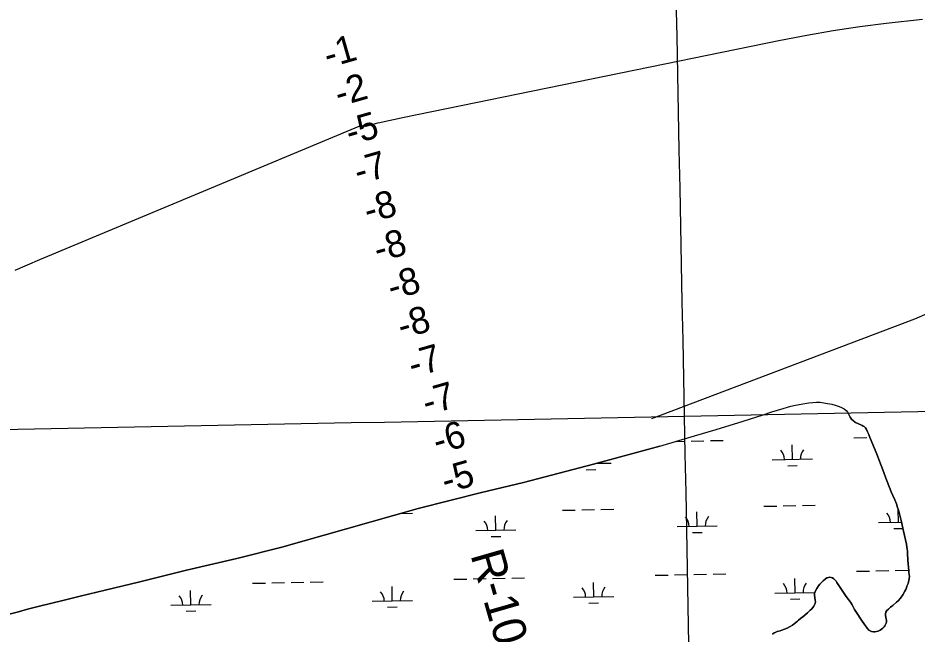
# Model space of a CAD drawing. Extents: x 3989314 to 4027622, y 243956 to 270014.
# Drawn here: x 3997154 to 3999395, y 255017 to 256552 of the extents above; entities that cross this region are included whole.
import ezdxf

# ---------------------------------------------------------------- set-up
doc = ezdxf.new("R2010")
doc.units = 0
for name, color, linetype in [('V-GRID-MAJR', 7, 'Continuous'), ('V-RIVR-EDGE', 7, 'Continuous'), ('V-RIVR-RANG', 7, 'Continuous'), ('V-RIVR-RANG-IDEN', 7, 'Continuous'), ('V-TOPO-MINR', 7, 'Continuous'), ('V-TOPO-SHOR', 7, 'Continuous'), ('V-WETL-SWMP', 7, 'Continuous')]:
    doc.layers.add(name, color=color, linetype=linetype)

msp = doc.modelspace()

# ---------------------------------------------------------------- linework, layer by layer
at = {"layer": 'V-GRID-MAJR'}
for points in [[(3998934.301, 249501.96300000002), (3998815.338, 255559.756), (3998696.338, 261619.472), (3998577.3370000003, 267679.178), (3998577.299, 267681.11100000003)], [(3993497.629, 255455.714), (3998815.338, 255559.756), (4004133.032, 255664.571), (4009450.711, 255770.161), (4014768.3740000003, 255876.52300000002), (4020086.022, 255983.659), (4025403.6550000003, 256091.568)]]:
    msp.add_spline(points, degree=3, dxfattribs=at)
at = {"layer": 'V-RIVR-EDGE'}
for points in [[(3998754.062, 255484.529), (3998840.193, 255510.33000000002), (3998894.25, 255526.067), (3998961.758, 255546.83800000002), (3999011.549, 255562.57700000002), (3999033.018, 255570.06), (3999060.824, 255578.96300000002), (3999072.073, 255582.18600000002), (3999080.091, 255584.38), (3999092.248, 255587.087), (3999115.268, 255591.339), (3999124.965, 255592.75400000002), (3999134.791, 255593.651), (3999144.233, 255594.29200000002), (3999153.67, 255594.286)], [(3998754.062, 255484.529), (3998588.223, 255440.24300000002), (3998414.323, 255394.41700000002), (3998309.677, 255369.211)], [(3998309.677, 255369.211), (3998151.833, 255329.68), (3997973.356, 255278.578), (3997811.755, 255233.279), (3997699.774, 255204.988), (3997574.289, 255175.671), (3997458.34, 255146.575), (3997371.574, 255125.69700000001), (3997309.028, 255111.04), (3997269.123, 255101.009), (3997207.771, 255085.956), (3997177.989, 255078.331), (3997155.356, 255072.117), (3997092.221, 255056.266)], [(3999034.941, 255016.748), (3999038.677, 255019.41400000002), (3999041.378, 255020.93600000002), (3999046.387, 255022.695), (3999053.451, 255024.82700000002), (3999057.8170000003, 255026.336), (3999070.924, 255031.635), (3999078.383, 255035.43), (3999084.685, 255038.848), (3999092.934, 255045.844), (3999096.799, 255048.764), (3999099.764, 255051.437), (3999104.272, 255055.123), (3999110.197, 255059.313), (3999115.223, 255063.51200000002), (3999121.926, 255069.363), (3999128.7600000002, 255075.853), (3999132.631, 255079.673), (3999135.342, 255082.859), (3999137.931, 255086.55800000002), (3999139.489, 255089.753), (3999140.5360000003, 255092.95), (3999141.593, 255097.556), (3999141.2320000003, 255101.404), (3999139.262, 255113.592), (3999139.541, 255116.922), (3999140.075, 255120.37900000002), (3999141.64, 255124.34100000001), (3999144.753, 255130.08800000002), (3999149.154, 255136.72400000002), (3999152.386, 255140.932), (3999154.968, 255143.863), (3999160.645, 255149.59100000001), (3999166.9590000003, 255154.676), (3999170.1750000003, 255156.45), (3999173.773, 255157.707), (3999177.619, 255158.068), (3999180.949, 255157.78900000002), (3999184.017, 255156.745), (3999187.335, 255154.41400000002), (3999190.2660000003, 255151.70500000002), (3999193.061, 255148.354), (3999195.095, 255145.522), (3999218.571, 255110.122), (3999223.9080000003, 255103.165), (3999228.602, 255096.085), (3999232.915, 255089.136), (3999239.1210000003, 255077.946), (3999243.815, 255070.481), (3999256.633, 255051.431), (3999263.484, 255040.619), (3999266.279, 255037.14), (3999268.563, 255033.537), (3999270.34, 255031.09), (3999274.7970000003, 255026.44700000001), (3999277.7290000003, 255024.377), (3999280.924, 255023.074), (3999286.171, 255021.886), (3999289.632, 255021.991), (3999293.997, 255022.859), (3999298.234, 255024.114), (3999303.116, 255026.132), (3999309.433, 255031.34600000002), (3999312.656, 255034.655), (3999314.596, 255037.078), (3999316.412, 255040.39800000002), (3999317.715, 255043.46600000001), (3999318.505, 255047.05000000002), (3999318.528, 255050.124), (3999317.915, 255054.61500000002), (3999316.048, 255062.957), (3999315.818, 255066.932), (3999317.129, 255071.409), (3999319.847, 255075.364)], [(3999319.847, 255075.364), (3999323.33, 255078.929), (3999328.745, 255083.764), (3999331.707, 255086.05000000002), (3999334.541, 255087.95500000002), (3999343.823, 255096.22400000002), (3999347.433, 255099.661), (3999353.628, 255106.413), (3999359.322, 255114.579), (3999364.505, 255123.38700000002), (3999366.5840000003, 255127.602), (3999368.2800000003, 255131.95), (3999369.588, 255136.04200000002), (3999372.873, 255142.685)]]:
    msp.add_lwpolyline(points, dxfattribs=at)
at = {"layer": 'V-TOPO-MINR'}
for points in [[(3999408.762457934, 256548.33119505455), (3999318.2285450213, 256538.05911623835), (3999251.9537520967, 256529.63691733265), (3999185.8666386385, 256520.03456851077), (3999120.061044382, 256508.66199481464), (3999054.4431295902, 256496.1092712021), (3998112.928943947, 256302.860964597), (3998101.50308511, 256300.49334681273), (3998090.083296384, 256298.09706968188), (3998078.672612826, 256295.65780353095), (3998067.2679993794, 256293.18987803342), (3998056.40921246, 256290.818654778), (3998050.451044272, 256289.46448715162), (3998044.5095303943, 256288.04321957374), (3998038.592997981, 256286.52130206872), (3998032.693119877, 256284.9322846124), (3998020.949933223, 256281.662323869), (3998020.93407441, 256281.65891151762), (3998020.9020265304, 256281.65652885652), (3998020.804536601, 256281.66769528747), (3998020.772078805, 256281.6722006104), (3998020.755873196, 256281.6746210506), (3998014.8955401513, 256282.57647257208), (3998011.979755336, 256282.77903929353), (3998009.1022672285, 256282.66742615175), (3998006.2822241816, 256282.08454321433), (3998003.5004778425, 256281.18748041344), (3997208.3145577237, 255949.39935462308), (3997146.5055219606, 255922.6533061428)], [(3998734.21, 255554.1), (3999389.2295445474, 255802.18688364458), (3999419.692060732, 255815.1619594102)]]:
    msp.add_lwpolyline(points, dxfattribs=at)
at = {"layer": 'V-TOPO-SHOR'}
for points in [[(3999153.67, 255594.286), (3999166.988, 255592.465), (3999182.241, 255589.86800000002), (3999191.034, 255587.407), (3999198.529, 255584.945), (3999205.253, 255582.352), (3999213.007, 255578.34), (3999218.0470000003, 255573.812), (3999221.4050000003, 255569.413), (3999228.379, 255557.125)], [(3999361.267, 255272.881), (3999354.949, 255300.046), (3999351.47, 255316.602), (3999348.629, 255325.658), (3999346.1780000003, 255332.256), (3999343.466, 255340.795), (3999339.464, 255351.014), (3999334.815, 255362.01200000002), (3999330.4250000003, 255371.068), (3999320.3540000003, 255396.553), (3999317.256, 255405.22100000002), (3999311.835, 255418.934), (3999294.9220000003, 255464.602), (3999280.591, 255499.404), (3999277.492, 255506.39), (3999274.522, 255513.894), (3999271.5530000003, 255520.492), (3999268.5810000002, 255526.44400000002), (3999265.9960000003, 255530.714), (3999264.446, 255532.39500000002), (3999262.896, 255533.69), (3999260.438, 255534.986), (3999257.8540000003, 255536.151), (3999254.4930000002, 255537.964), (3999241.562, 255543.923), (3999239.106, 255545.347), (3999237.038, 255547.03), (3999231.738, 255552.337), (3999228.379, 255557.125)], [(3999372.873, 255142.685), (3999375.171, 255154.373), (3999375.642, 255160.863), (3999375.4110000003, 255164.624), (3999374.43, 255171.208), (3999374.364, 255174.36800000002), (3999372.23, 255200.52300000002), (3999371.321, 255218.298), (3999370.842, 255223.17), (3999369.537, 255232.83000000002), (3999368.222, 255240.529), (3999361.267, 255272.881)]]:
    msp.add_lwpolyline(points, dxfattribs=at)
at = {"layer": 'V-WETL-SWMP'}
for p, q in [((3999092.248, 255587.087), (3999115.267, 255591.33800000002)), ((3999115.267, 255591.33800000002), (3999124.965, 255592.753)), ((3999124.965, 255592.75300000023), (3999134.792, 255593.65100000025)), ((3999134.792, 255593.651), (3999144.2320000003, 255594.291)), ((3999144.2320000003, 255594.291), (3999153.67, 255594.285)), ((3999153.67, 255594.285), (3999166.987, 255592.465)), ((3999166.987, 255592.465), (3999182.242, 255589.86900000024)), ((3999182.242, 255589.86900000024), (3999191.0330000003, 255587.40600000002)), ((3999011.549, 255562.57600000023), (3999033.018, 255570.06100000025)), ((3999033.018, 255570.06100000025), (3999060.823, 255578.96300000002)), ((3999060.823, 255578.96300000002), (3999072.074, 255582.187)), ((3999072.074, 255582.187), (3999080.092, 255584.38)), ((3999080.092, 255584.38000000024), (3999092.248, 255587.087)), ((3999191.0330000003, 255587.40600000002), (3999198.5300000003, 255584.94400000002)), ((3999198.5300000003, 255584.94400000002), (3999205.252, 255582.35300000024)), ((3999205.252, 255582.35300000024), (3999213.007, 255578.34000000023)), ((3999213.007, 255578.34000000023), (3999218.0470000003, 255573.81100000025)), ((3999218.0470000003, 255573.81100000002), (3999221.4050000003, 255569.412)), ((3999221.4050000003, 255569.412), (3999228.379, 255557.12400000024)), ((3998894.25, 255526.06600000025), (3998961.758, 255546.83700000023)), ((3998961.758, 255546.83700000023), (3999011.549, 255562.57600000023)), ((3999228.379, 255557.12400000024), (3999231.738, 255552.336)), ((3999231.738, 255552.336), (3999237.037, 255547.02999999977)), ((3999237.037, 255547.03000000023), (3999239.106, 255545.34700000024)), ((3999239.106, 255545.347), (3999241.562, 255543.92299999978)), ((3999241.562, 255543.923), (3999254.492, 255537.964)), ((3998840.1920000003, 255510.33000000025), (3998894.25, 255526.06600000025)), ((3999254.492, 255537.964), (3999257.853, 255536.15100000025)), ((3999257.853, 255536.15100000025), (3999260.4390000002, 255534.98500000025)), ((3999260.4390000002, 255534.98500000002), (3999262.895, 255533.69)), ((3999262.895, 255533.69), (3999264.447, 255532.396)), ((3999264.447, 255532.396), (3999265.997, 255530.71300000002)), ((3999265.997, 255530.71300000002), (3999268.5810000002, 255526.443)), ((3999268.5810000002, 255526.443), (3999271.552, 255520.49200000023)), ((3999271.552, 255520.49200000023), (3999274.522, 255513.894)), ((3998754.061, 255484.53), (3998840.1920000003, 255510.33000000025)), ((3998831.8552527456, 255497.66252674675), (3998863.8488999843, 255498.3001288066)), ((3998879.8457236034, 255498.61892983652), (3998911.839370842, 255499.25653189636)), ((3999237.6826703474, 255505.7502697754), (3999269.676317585, 255506.38787183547)), ((3999274.522, 255513.894), (3999277.491, 255506.39)), ((3999277.491, 255506.39), (3999280.591, 255499.40400000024)), ((3999280.591, 255499.40400000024), (3999294.923, 255464.602)), ((3998588.223, 255440.24300000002), (3998754.061, 255484.53)), ((3998795.4828693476, 255496.93766076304), (3998815.858429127, 255497.34372571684)), ((3999084.1323981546, 255451.93808771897), (3999083.415095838, 255487.9309408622)), ((3999294.923, 255464.602), (3999311.8340000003, 255418.93500000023)), ((3998414.323, 255394.418), (3998588.223, 255440.24300000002)), ((3998595.555848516, 255442.20123552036), (3998632.314112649, 255442.9337917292)), ((3999034.1423243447, 255450.94183450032), (3999134.122471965, 255452.93434093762)), ((3999072.4422441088, 255436.27105036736), (3999096.437479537, 255436.74925191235)), ((3998570.633884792, 255426.27050115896), (3998594.6291202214, 255426.74870270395)), ((3999311.8340000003, 255418.93500000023), (3999317.256, 255405.22100000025)), ((3998309.676, 255369.211), (3998414.323, 255394.418)), ((3999317.256, 255405.22100000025), (3999320.3540000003, 255396.554)), ((3999320.3540000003, 255396.554), (3999330.4250000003, 255371.068)), ((3998151.833, 255329.68100000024), (3998309.676, 255369.21100000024)), ((3999330.4250000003, 255371.068), (3999334.816, 255362.011)), ((3999334.816, 255362.011), (3999339.464, 255351.014)), ((3999339.464, 255351.014), (3999343.467, 255340.794)), ((3997973.3570000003, 255278.57800000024), (3998151.833, 255329.68100000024)), ((3998511.230602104, 255325.06579538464), (3998543.224249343, 255325.70339744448)), ((3998559.221072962, 255326.02219847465), (3998591.2147202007, 255326.65980053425)), ((3998607.2115438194, 255326.97860156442), (3998639.205191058, 255327.61620362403)), ((3998846.9332483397, 255285.31680109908), (3998846.215946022, 255321.30965424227)), ((3999013.0389614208, 255335.06634459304), (3999045.032608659, 255335.70394665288)), ((3999061.029432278, 255336.02274768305), (3999093.0230795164, 255336.66034974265)), ((3999109.0199031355, 255336.97915077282), (3999141.013550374, 255337.61675283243)), ((3999343.467, 255340.794), (3999346.177, 255332.256)), ((3999346.177, 255332.256), (3999348.63, 255325.65800000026)), ((3999348.741607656, 255295.31735030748), (3999348.109021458, 255327.05931121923)), ((3999348.63, 255325.65800000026), (3999351.469, 255316.602)), ((3998107.622745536, 255317.02228603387), (3998137.396831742, 255317.61565441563)), ((3998345.124889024, 255275.31625189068), (3998344.4075867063, 255311.30910503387)), ((3999351.469, 255316.602), (3999354.949, 255300.045)), ((3999354.949, 255300.045), (3999361.268, 255272.88)), ((3997811.754, 255233.27800000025), (3997973.3570000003, 255278.57800000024)), ((3998295.1348152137, 255274.31999867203), (3998395.1149628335, 255276.31250510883)), ((3998796.9431745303, 255284.32054788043), (3998896.9233221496, 255286.31305431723)), ((3999298.751533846, 255294.32109708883), (3999356.015006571, 255295.4623020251)), ((3999337.0514536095, 255279.65031295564), (3999359.5886424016, 255280.09945705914)), ((3998333.434734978, 255259.6492145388), (3998357.4299704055, 255260.12741608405)), ((3998835.243094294, 255269.64976374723), (3998859.238329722, 255270.12796529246)), ((3999361.268, 255272.88), (3999368.222, 255240.52800000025)), ((3997699.775, 255204.98700000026), (3997811.754, 255233.27800000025)), ((3999368.222, 255240.52800000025), (3999369.538, 255232.831)), ((3999369.538, 255232.831), (3999370.841, 255223.169)), ((3999370.841, 255223.169), (3999371.322, 255218.297)), ((3999371.322, 255218.297), (3999372.23, 255200.52300000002)), ((3997574.29, 255175.67000000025), (3997699.775, 255204.98700000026)), ((3999372.23, 255200.52300000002), (3999374.364, 255174.36900000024)), ((3997458.34, 255146.575), (3997574.29, 255175.67000000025)), ((3998742.502881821, 255163.14076447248), (3998774.496529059, 255163.77836653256)), ((3998790.4933526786, 255164.09716756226), (3998822.486999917, 255164.73476962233)), ((3998838.483823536, 255165.05357065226), (3998870.477470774, 255165.6911727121)), ((3998886.474294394, 255166.009973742), (3998918.467941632, 255166.64757580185)), ((3999244.311241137, 255173.14131368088), (3999276.3048883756, 255173.778915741)), ((3999292.301711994, 255174.09771677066), (3999324.295359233, 255174.73531883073)), ((3999340.292182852, 255175.05411986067), (3999372.2858300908, 255175.6917219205)), ((3999374.364, 255174.36900000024), (3999374.429, 255171.20800000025)), ((3999374.429, 255171.20800000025), (3999375.41, 255164.623)), ((3999375.41, 255164.623), (3999375.642, 255160.86300000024)), ((3997371.573, 255125.698), (3997458.34, 255146.575)), ((3997738.8861631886, 255143.13966605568), (3997770.879810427, 255143.77726811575)), ((3997786.876634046, 255144.09606914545), (3997818.870281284, 255144.73367120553)), ((3997834.8671049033, 255145.05247223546), (3997866.860752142, 255145.6900742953)), ((3997882.857575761, 255146.0088753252), (3997914.851223, 255146.64647738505)), ((3998240.6945225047, 255153.14021526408), (3998272.6881697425, 255153.77781732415)), ((3998288.6849933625, 255154.09661835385), (3998320.6786406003, 255154.73422041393)), ((3998336.67546422, 255155.05302144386), (3998368.669111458, 255155.6906235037)), ((3998384.6659350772, 255156.0094245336), (3998416.6595823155, 255156.64702659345)), ((3998588.952609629, 255109.32858241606), (3998588.235307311, 255145.32143555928)), ((3999090.7609689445, 255119.32913162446), (3999090.043666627, 255155.32198476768)), ((3999152.386, 255140.93200000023), (3999149.1550000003, 255136.72400000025)), ((3999154.969, 255143.863), (3999152.386, 255140.93200000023)), ((3999160.646, 255149.59200000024), (3999154.969, 255143.863)), ((3999166.9590000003, 255154.67700000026), (3999160.646, 255149.59200000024)), ((3999170.1750000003, 255156.45), (3999166.9590000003, 255154.677)), ((3999173.772, 255157.70800000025), (3999170.1750000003, 255156.45000000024)), ((3999177.619, 255158.068), (3999173.772, 255157.70800000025)), ((3999180.949, 255157.78900000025), (3999177.619, 255158.068)), ((3999184.018, 255156.74400000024), (3999180.949, 255157.78900000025)), ((3999187.335, 255154.41500000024), (3999184.018, 255156.74400000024)), ((3999190.265, 255151.70400000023), (3999187.335, 255154.41500000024)), ((3999193.062, 255148.35400000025), (3999190.265, 255151.70400000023)), ((3999195.094, 255145.521), (3999193.062, 255148.35400000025)), ((3999218.571, 255110.122), (3999195.094, 255145.521)), ((3999372.8740000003, 255142.68600000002), (3999369.588, 255136.041)), ((3999375.1720000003, 255154.374), (3999372.8740000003, 255142.68600000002)), ((3999375.642, 255160.86300000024), (3999375.1720000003, 255154.374)), ((3997309.029, 255111.04), (3997371.573, 255125.698)), ((3997585.3358909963, 255089.32748399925), (3997584.618588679, 255125.32033714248)), ((3998087.1442503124, 255099.32803320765), (3998086.426947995, 255135.32088635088)), ((3999040.770895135, 255118.3328784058), (3999140.0655690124, 255120.31172402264)), ((3999140.076, 255120.37900000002), (3999139.54, 255116.92200000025)), ((3999141.64, 255124.34200000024), (3999140.076, 255120.37900000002)), ((3999144.753, 255130.08800000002), (3999141.64, 255124.34200000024)), ((3999149.1550000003, 255136.72400000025), (3999144.753, 255130.08800000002)), ((3999364.506, 255123.38700000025), (3999359.322, 255114.57800000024)), ((3999366.585, 255127.60200000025), (3999364.506, 255123.38700000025)), ((3999368.279, 255131.949), (3999366.585, 255127.60200000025)), ((3999369.588, 255136.041), (3999368.279, 255131.949)), ((3997207.771, 255085.95500000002), (3997269.122, 255101.00800000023)), ((3997269.122, 255101.00800000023), (3997309.029, 255111.04000000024)), ((3998037.1541765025, 255098.331779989), (3998137.1343241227, 255100.3242864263)), ((3998538.9625358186, 255108.3323291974), (3998638.9426834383, 255110.3248356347)), ((3999079.0708148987, 255103.66209427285), (3999103.0660503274, 255104.14029581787)), ((3999139.54, 255116.92200000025), (3999139.262, 255113.59200000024)), ((3999139.262, 255113.59200000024), (3999141.2320000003, 255101.403)), ((3999141.592, 255097.556), (3999140.5360000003, 255092.94900000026)), ((3999141.2320000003, 255101.403), (3999141.592, 255097.556)), ((3999223.9080000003, 255103.16600000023), (3999218.571, 255110.122)), ((3999228.603, 255096.08600000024), (3999223.9080000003, 255103.16600000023)), ((3999232.915, 255089.13700000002), (3999228.603, 255096.08600000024)), ((3999343.822, 255096.225), (3999334.54, 255087.95500000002)), ((3999347.433, 255099.661), (3999343.822, 255096.225)), ((3999353.629, 255106.41300000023), (3999347.433, 255099.661)), ((3999359.322, 255114.57800000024), (3999353.629, 255106.41300000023)), ((3997155.3570000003, 255072.117), (3997177.989, 255078.332)), ((3997177.989, 255078.332), (3997207.771, 255085.95500000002)), ((3997535.3458171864, 255088.3312307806), (3997635.3259648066, 255090.3237372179)), ((3997573.64573695, 255073.66044664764), (3997597.6409723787, 255074.13864819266)), ((3998075.4540962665, 255083.66099585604), (3998099.4493316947, 255084.13919740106)), ((3998577.2624555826, 255093.66154506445), (3998601.257691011, 255094.13974660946)), ((3999128.761, 255075.85300000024), (3999121.9250000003, 255069.36200000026)), ((3999132.631, 255079.673), (3999128.761, 255075.85300000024)), ((3999135.343, 255082.859), (3999132.631, 255079.673)), ((3999137.931, 255086.55800000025), (3999135.343, 255082.859)), ((3999139.49, 255089.75200000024), (3999137.931, 255086.55800000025)), ((3999140.5360000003, 255092.94900000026), (3999139.49, 255089.75200000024)), ((3999239.1210000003, 255077.94600000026), (3999232.915, 255089.13700000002)), ((3999243.8140000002, 255070.48200000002), (3999239.1210000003, 255077.94600000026)), ((3999319.846, 255075.364), (3999317.129, 255071.409)), ((3999323.33, 255078.93000000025), (3999319.846, 255075.364)), ((3999328.745, 255083.764), (3999323.33, 255078.93000000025)), ((3999331.707, 255086.051), (3999328.745, 255083.764)), ((3999334.54, 255087.95500000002), (3999331.707, 255086.051)), ((3997092.22, 255056.26600000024), (3997155.3570000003, 255072.117)), ((3999099.764, 255051.437), (3999096.798, 255048.76500000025)), ((3999104.273, 255055.12400000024), (3999099.764, 255051.437)), ((3999110.196, 255059.31400000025), (3999104.273, 255055.12400000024)), ((3999115.222, 255063.51100000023), (3999110.196, 255059.31400000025)), ((3999121.9250000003, 255069.362), (3999115.222, 255063.511)), ((3999256.633, 255051.43), (3999243.8140000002, 255070.48200000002)), ((3999263.483, 255040.619), (3999256.633, 255051.43)), ((3999317.129, 255071.409), (3999315.818, 255066.932)), ((3999315.818, 255066.932), (3999316.048, 255062.957)), ((3999316.048, 255062.957), (3999317.915, 255054.61500000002)), ((3999317.915, 255054.61500000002), (3999318.5270000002, 255050.125)), ((3999318.5270000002, 255050.125), (3999318.506, 255047.049)), ((3999070.9250000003, 255031.634), (3999057.818, 255026.337)), ((3999078.383, 255035.43), (3999070.9250000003, 255031.634)), ((3999084.686, 255038.848), (3999078.383, 255035.43)), ((3999092.934, 255045.843), (3999084.686, 255038.848)), ((3999096.798, 255048.76500000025), (3999092.934, 255045.843)), ((3999266.279, 255037.14000000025), (3999263.483, 255040.619)), ((3999268.563, 255033.537), (3999266.279, 255037.14000000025)), ((3999270.341, 255031.09000000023), (3999268.563, 255033.537)), ((3999274.796, 255026.44700000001), (3999270.341, 255031.09000000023)), ((3999309.432, 255031.345), (3999303.117, 255026.132)), ((3999312.657, 255034.65600000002), (3999309.432, 255031.345)), ((3999314.596, 255037.07800000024), (3999312.657, 255034.65600000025)), ((3999316.412, 255040.39800000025), (3999314.596, 255037.07800000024)), ((3999317.714, 255043.46600000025), (3999316.412, 255040.39800000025)), ((3999318.506, 255047.049), (3999317.714, 255043.46600000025)), ((3999038.676, 255019.41400000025), (3999034.9420000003, 255016.74800000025)), ((3999041.377, 255020.935), (3999038.676, 255019.41400000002)), ((3999046.387, 255022.69600000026), (3999041.377, 255020.935)), ((3999053.45, 255024.82800000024), (3999046.387, 255022.69600000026)), ((3999057.818, 255026.337), (3999053.45, 255024.82799999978)), ((3999277.73, 255024.377), (3999274.796, 255026.44700000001)), ((3999280.9250000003, 255023.074), (3999277.73, 255024.377)), ((3999286.1720000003, 255021.886), (3999280.9250000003, 255023.074)), ((3999289.633, 255021.991), (3999286.1720000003, 255021.886)), ((3999293.9960000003, 255022.86000000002), (3999289.633, 255021.991)), ((3999298.234, 255024.114), (3999293.9960000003, 255022.86000000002)), ((3999303.117, 255026.132), (3999298.234, 255024.114))]:
    msp.add_line(p, q, dxfattribs=at)
for centre, radius, start, end in [((3999139.3549067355, 255453.51351570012), 35.246287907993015, 140.36987458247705, 181.91353291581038), ((3999028.890968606, 255451.3120775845), 35.24628790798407, 0.3698775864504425, 41.913535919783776), ((3998637.54654742, 255443.51296649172), 35.246287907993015, 179.20299452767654, 181.91353291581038), ((3998289.8834594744, 255274.69024175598), 35.24628790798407, 0.3698775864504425, 41.913535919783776), ((3998400.347397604, 255276.8916798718), 35.246287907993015, 140.36987458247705, 181.91353291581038), ((3998791.6918187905, 255284.69079096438), 35.24628790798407, 0.3698775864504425, 41.913535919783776), ((3998902.15575692, 255286.8922290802), 35.246287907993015, 140.36987458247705, 181.91353291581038), ((3999293.5001781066, 255294.69134017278), 35.24628790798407, 0.3698775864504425, 41.913535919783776), ((3999035.519539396, 255118.70312149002), 35.24628790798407, 0.3698775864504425, 41.913535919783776), ((3999145.9834775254, 255120.9045596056), 35.246287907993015, 140.36987458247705, 181.91353291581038), ((3998031.9028207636, 255098.70202307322), 35.24628790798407, 0.3698775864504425, 41.913535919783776), ((3998142.3667588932, 255100.9034611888), 35.246287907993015, 140.36987458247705, 181.91353291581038), ((3998533.7111800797, 255108.70257228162), 35.24628790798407, 0.3698775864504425, 41.913535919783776), ((3998644.175118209, 255110.9040103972), 35.246287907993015, 140.36987458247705, 181.91353291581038), ((3997530.094461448, 255088.70147386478), 35.24628790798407, 0.3698775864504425, 41.913535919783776), ((3997640.558399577, 255090.9029119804), 35.246287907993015, 140.36987458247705, 181.91353291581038)]:
    msp.add_arc(centre, radius, start, end, dxfattribs=at)

# ---------------------------------------------------------------- texts
at = {"layer": 'V-RIVR-RANG'}
for s, p in [('-1', (3997926.7702356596, 256426.62281819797)), ('-2', (3997954.116273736, 256330.35088320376)), ('-5', (3997981.5704935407, 256234.131799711)), ('-7', (3998002.3369150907, 256136.22218881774)), ('-8', (3998026.6847133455, 256039.38271621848)), ('-8', (3998051.274713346, 255942.3027162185)), ('-8', (3998085.714713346, 255848.17271621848)), ('-8', (3998110.6547133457, 255751.31271621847)), ('-7', (3998137.6769150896, 255654.88218881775)), ('-7', (3998172.5369150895, 255560.97218881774)), ('-6', (3998198.891823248, 255464.32817447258)), ('-5', (3998220.0904935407, 255366.33179971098))]:
    msp.add_text(s, height=67, rotation=16.00488888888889, dxfattribs=at).set_placement(p)
at = {"layer": 'V-RIVR-RANG-IDEN'}
msp.add_text('R-10.5', height=82.999998, rotation=286.0035710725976, dxfattribs=at).set_placement((3998281.3918510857, 255214.20754113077))

doc.saveas('drawing.dxf')
